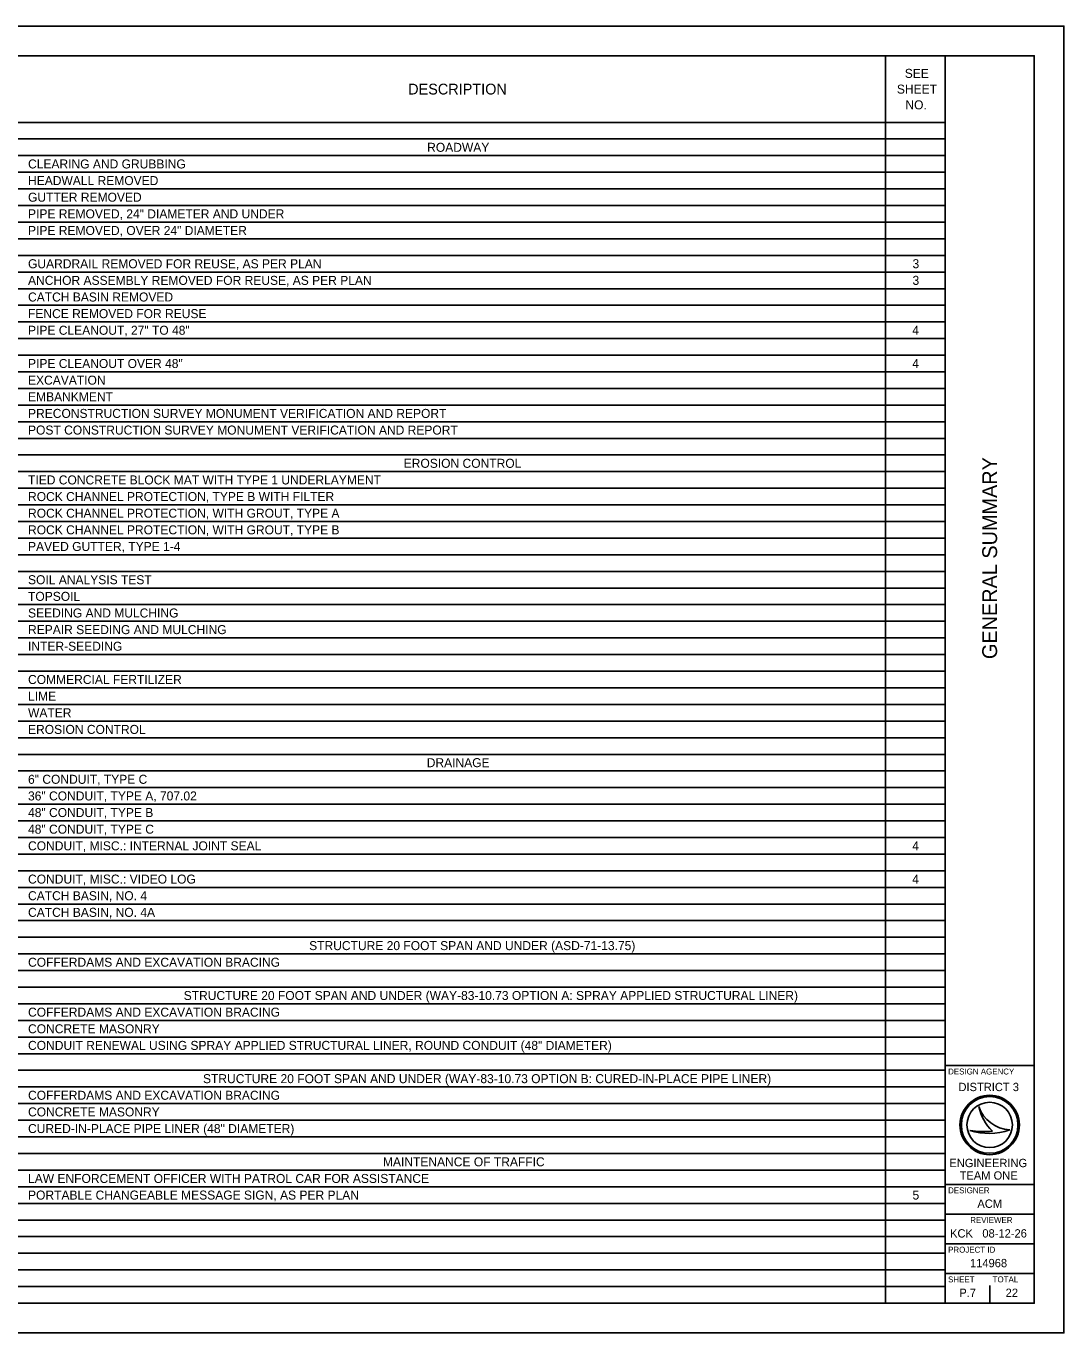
# Model space of a CAD drawing. Extents: x 0 to 34, y 0 to 22.
# Drawn here: x 16.52 to 34, y 0 to 22 of the extents above; entities that cross this region are included whole.
import ezdxf

# ---------------------------------------------------------------- set-up
doc = ezdxf.new("R2010")
doc.units = 0
for name, color, linetype in [('SH_Border', 7, 'Continuous'), ('SH_Cut_Line', 7, 'Continuous'), ('SH_Data', 7, 'Continuous'), ('SH_Text', 7, 'Continuous')]:
    doc.layers.add(name, color=color, linetype=linetype)

msp = doc.modelspace()

# ---------------------------------------------------------------- linework, layer by layer
at = {"layer": 'SH_Border'}
for p, q in [((32, 0.5), (32, 21.5)), ((32, 4.5), (33.5, 4.5)), ((32, 2.5), (33.5, 2.5)), ((32, 2), (33.5, 2)), ((32, 1.5), (33.5, 1.5)), ((32, 1), (33.5, 1))]:
    msp.add_line(p, q, dxfattribs=at)
msp.add_lwpolyline([(1.5, 21.5), (33.5, 21.5), (33.5, 0.5), (1.5, 0.5)], close=True, dxfattribs=at)
at = {"layer": 'SH_Cut_Line'}
msp.add_lwpolyline([(0, 0), (34, 0), (34, 22), (0, 22)], close=True, dxfattribs=at)
at = {"layer": 'SH_Data'}
for p, q in [((32.567, 3.81), (32.567, 3.81)), ((32.417, 3.41), (32.417, 3.41)), ((32.75, 3.5), (32.75, 3.5)), ((33.087, 3.419), (33.087, 3.419)), ((32.375, 0.675), (32.375, 0.675)), ((32.75, 0.5), (32.75, 0.8))]:
    msp.add_line(p, q, dxfattribs=at)
for radius in [0.5, 0.477, 0.477, 0.382]:
    msp.add_circle((32.75, 3.5), radius, dxfattribs=at)
for centre, radius, start, end in [((33.116, 3.998), 0.58, 198.9257, 198.9319), ((33.347, 3.97), 0.796, 191.6379, 191.6421), ((33.116, 3.998), 0.58, 198.9319, 267.1657), ((33.347, 3.97), 0.796, 191.6421, 226.0947), ((32.739, 4.37), 1.013, 251.4576, 290.0832), ((32.648, 4.654), 1.266, 259.4964, 259.4995), ((32.739, 4.37), 1.013, 251.4527, 251.4576), ((32.648, 4.654), 1.266, 259.4995, 276.6672)]:
    msp.add_arc(centre, radius, start, end, dxfattribs=at)
at = {"layer": 'SH_Text'}
for p, q in [((1.5, 21.5), (32, 21.5)), ((30.995, 21.5), (30.995, 0.5)), ((32, 21.5), (32, 0.5)), ((1.5, 20.38), (32, 20.38)), ((1.5, 20.1), (32, 20.1)), ((1.5, 19.82), (32, 19.82)), ((1.5, 19.54), (32, 19.54)), ((1.5, 19.26), (32, 19.26)), ((1.5, 18.98), (32, 18.98)), ((1.5, 18.7), (32, 18.7)), ((1.5, 18.42), (32, 18.42)), ((1.5, 18.14), (32, 18.14)), ((1.5, 17.86), (32, 17.86)), ((1.5, 17.58), (32, 17.58)), ((1.5, 17.3), (32, 17.3)), ((1.5, 17.02), (32, 17.02)), ((1.5, 16.74), (32, 16.74)), ((1.5, 16.46), (32, 16.46)), ((1.5, 16.18), (32, 16.18)), ((1.5, 15.9), (32, 15.9)), ((1.5, 15.62), (32, 15.62)), ((1.5, 15.34), (32, 15.34)), ((1.5, 15.06), (32, 15.06)), ((1.5, 14.78), (32, 14.78)), ((1.5, 14.5), (32, 14.5)), ((1.5, 14.22), (32, 14.22)), ((1.5, 13.94), (32, 13.94)), ((1.5, 13.66), (32, 13.66)), ((1.5, 13.38), (32, 13.38)), ((1.5, 13.1), (32, 13.1)), ((1.5, 12.82), (32, 12.82)), ((1.5, 12.54), (32, 12.54)), ((1.5, 12.26), (32, 12.26)), ((1.5, 11.98), (32, 11.98)), ((1.5, 11.7), (32, 11.7)), ((1.5, 11.42), (32, 11.42)), ((1.5, 11.14), (32, 11.14)), ((1.5, 10.86), (32, 10.86)), ((1.5, 10.58), (32, 10.58)), ((1.5, 10.3), (32, 10.3)), ((1.5, 10.02), (32, 10.02)), ((1.5, 9.74), (32, 9.74)), ((1.5, 9.46), (32, 9.46)), ((1.5, 9.18), (32, 9.18)), ((1.5, 8.9), (32, 8.9)), ((1.5, 8.62), (32, 8.62)), ((1.5, 8.34), (32, 8.34)), ((1.5, 8.06), (32, 8.06)), ((1.5, 7.78), (32, 7.78)), ((1.5, 7.5), (32, 7.5)), ((1.5, 7.22), (32, 7.22)), ((1.5, 6.94), (32, 6.94)), ((1.5, 6.66), (32, 6.66)), ((1.5, 6.38), (32, 6.38)), ((1.5, 6.1), (32, 6.1)), ((1.5, 5.82), (32, 5.82)), ((1.5, 5.54), (32, 5.54)), ((1.5, 5.26), (32, 5.26)), ((1.5, 4.98), (32, 4.98)), ((1.5, 4.7), (32, 4.7)), ((1.5, 4.42), (32, 4.42)), ((1.5, 4.14), (32, 4.14)), ((1.5, 3.86), (32, 3.86)), ((1.5, 3.58), (32, 3.58)), ((1.5, 3.3), (32, 3.3)), ((1.5, 3.02), (32, 3.02)), ((1.5, 2.74), (32, 2.74)), ((1.5, 2.46), (32, 2.46)), ((1.5, 2.18), (32, 2.18)), ((1.5, 1.9), (32, 1.9)), ((1.5, 1.62), (32, 1.62)), ((1.5, 1.34), (32, 1.34)), ((1.5, 1.06), (32, 1.06)), ((1.5, 0.78), (32, 0.78)), ((1.5, 0.5), (32, 0.5))]:
    msp.add_line(p, q, dxfattribs=at)

# ---------------------------------------------------------------- texts
at = {"layer": 'SH_Data'}
msp.add_text('GENERAL SUMMARY', height=0.25, rotation=90, dxfattribs=at).set_placement((32.875, 11.344))
for s, height, p in [('DESIGN AGENCY', 0.1, (32.05, 4.35)), ('DISTRICT 3', 0.14, (32.224, 4.07)), ('ENGINEERING', 0.14, (32.071, 2.79)), ('TEAM ONE', 0.14, (32.244, 2.58)), ('DESIGNER', 0.1, (32.05, 2.35)), ('ACM', 0.14, (32.543, 2.105)), ('REVIEWER', 0.1, (32.422, 1.85)), ('KCK', 0.14, (32.083, 1.605)), ('08-12-26', 0.14, (32.627, 1.605)), ('PROJECT ID', 0.1, (32.05, 1.35)), ('114968', 0.14, (32.419, 1.105)), ('SHEET', 0.1, (32.05, 0.85)), ('TOTAL', 0.1, (32.8, 0.85)), ('P.7', 0.14, (32.239, 0.605)), ('22', 0.14, (33.019, 0.605))]:
    msp.add_text(s, height=height, dxfattribs=at).set_placement(p)
at = {"layer": 'SH_Text'}
for s, height, p in [('SEE ', 0.1515, (31.32, 21.129)), ('DESCRIPTION', 0.18184, (22.955, 20.849)), ('SHEET ', 0.1515, (31.187, 20.864)), ('NO.', 0.1515, (31.331, 20.599)), ('ROADWAY', 0.1515, (23.275, 19.884)), ('CLEARING AND GRUBBING', 0.15153, (16.552, 19.604)), ('HEADWALL REMOVED', 0.15153, (16.552, 19.324)), ('GUTTER REMOVED', 0.15153, (16.552, 19.044)), ('PIPE REMOVED, 24" DIAMETER AND UNDER', 0.15153, (16.552, 18.764)), ('PIPE REMOVED, OVER 24" DIAMETER', 0.15153, (16.552, 18.484)), ('GUARDRAIL REMOVED FOR REUSE, AS PER PLAN', 0.15153, (16.552, 17.924)), ('3', 0.152, (31.45, 17.924)), ('ANCHOR ASSEMBLY REMOVED FOR REUSE, AS PER PLAN', 0.15153, (16.552, 17.644)), ('3', 0.152, (31.45, 17.644)), ('CATCH BASIN REMOVED', 0.15153, (16.552, 17.364)), ('FENCE REMOVED FOR REUSE', 0.15153, (16.552, 17.084)), ('PIPE CLEANOUT, 27" TO 48"', 0.15153, (16.552, 16.804)), ('4', 0.152, (31.446, 16.804)), ('PIPE CLEANOUT OVER 48"', 0.15153, (16.552, 16.244)), ('4', 0.152, (31.446, 16.244)), ('EXCAVATION', 0.1515, (16.552, 15.964)), ('EMBANKMENT', 0.1515, (16.552, 15.684)), ('PRECONSTRUCTION SURVEY MONUMENT VERIFICATION AND REPORT', 0.15153, (16.552, 15.404)), ('POST CONSTRUCTION SURVEY MONUMENT VERIFICATION AND REPORT', 0.15153, (16.552, 15.124)), ('EROSION CONTROL', 0.15153, (22.88, 14.564)), ('TIED CONCRETE BLOCK MAT WITH TYPE 1 UNDERLAYMENT', 0.15153, (16.552, 14.284)), ('ROCK CHANNEL PROTECTION, TYPE B WITH FILTER', 0.15153, (16.552, 14.004)), ('ROCK CHANNEL PROTECTION, WITH GROUT, TYPE A', 0.15153, (16.552, 13.724)), ('ROCK CHANNEL PROTECTION, WITH GROUT, TYPE B', 0.15153, (16.552, 13.444)), ('PAVED GUTTER, TYPE 1-4', 0.15153, (16.552, 13.164)), ('SOIL ANALYSIS TEST', 0.15153, (16.552, 12.604)), ('TOPSOIL', 0.1515, (16.552, 12.324)), ('SEEDING AND MULCHING', 0.15153, (16.552, 12.044)), ('REPAIR SEEDING AND MULCHING', 0.15153, (16.552, 11.764)), ('INTER-SEEDING', 0.15153, (16.552, 11.484)), ('COMMERCIAL FERTILIZER', 0.15153, (16.552, 10.924)), ('LIME', 0.1515, (16.552, 10.644)), ('WATER', 0.1515, (16.552, 10.364)), ('EROSION CONTROL', 0.15153, (16.552, 10.084)), ('DRAINAGE', 0.1515, (23.268, 9.524)), ('6" CONDUIT, TYPE C', 0.15153, (16.552, 9.244)), ('36" CONDUIT, TYPE A, 707.02', 0.15153, (16.552, 8.964)), ('48" CONDUIT, TYPE B', 0.15153, (16.552, 8.684)), ('48" CONDUIT, TYPE C', 0.15153, (16.552, 8.404)), ('CONDUIT, MISC.: INTERNAL JOINT SEAL', 0.15153, (16.552, 8.124)), ('4', 0.152, (31.446, 8.124)), ('CONDUIT, MISC.: VIDEO LOG', 0.15153, (16.552, 7.564)), ('4', 0.152, (31.446, 7.564)), ('CATCH BASIN, NO. 4', 0.15153, (16.552, 7.284)), ('CATCH BASIN, NO. 4A', 0.15153, (16.552, 7.004)), ('STRUCTURE 20 FOOT SPAN AND UNDER (ASD-71-13.75)', 0.15153, (21.287, 6.444)), ('COFFERDAMS AND EXCAVATION BRACING', 0.15153, (16.552, 6.164)), ('STRUCTURE 20 FOOT SPAN AND UNDER (WAY-83-10.73 OPTION A: SPRAY APPLIED STRUCTURAL LINER)', 0.15153, (19.174, 5.604)), ('COFFERDAMS AND EXCAVATION BRACING', 0.15153, (16.552, 5.324)), ('CONCRETE MASONRY', 0.15153, (16.552, 5.044)), ('CONDUIT RENEWAL USING SPRAY APPLIED STRUCTURAL LINER, ROUND CONDUIT (48" DIAMETER)', 0.15153, (16.552, 4.764)), ('STRUCTURE 20 FOOT SPAN AND UNDER (WAY-83-10.73 OPTION B: CURED-IN-PLACE PIPE LINER)', 0.15153, (19.499, 4.204)), ('COFFERDAMS AND EXCAVATION BRACING', 0.15153, (16.552, 3.924)), ('CONCRETE MASONRY', 0.15153, (16.552, 3.644)), ('CURED-IN-PLACE PIPE LINER (48" DIAMETER)', 0.15153, (16.552, 3.364)), ('MAINTENANCE OF TRAFFIC', 0.15153, (22.53, 2.804)), ('LAW ENFORCEMENT OFFICER WITH PATROL CAR FOR ASSISTANCE', 0.15153, (16.552, 2.524)), ('PORTABLE CHANGEABLE MESSAGE SIGN, AS PER PLAN', 0.15153, (16.552, 2.244)), ('5', 0.152, (31.45, 2.244))]:
    msp.add_text(s, height=height, dxfattribs=at).set_placement(p)

doc.saveas('drawing.dxf')
